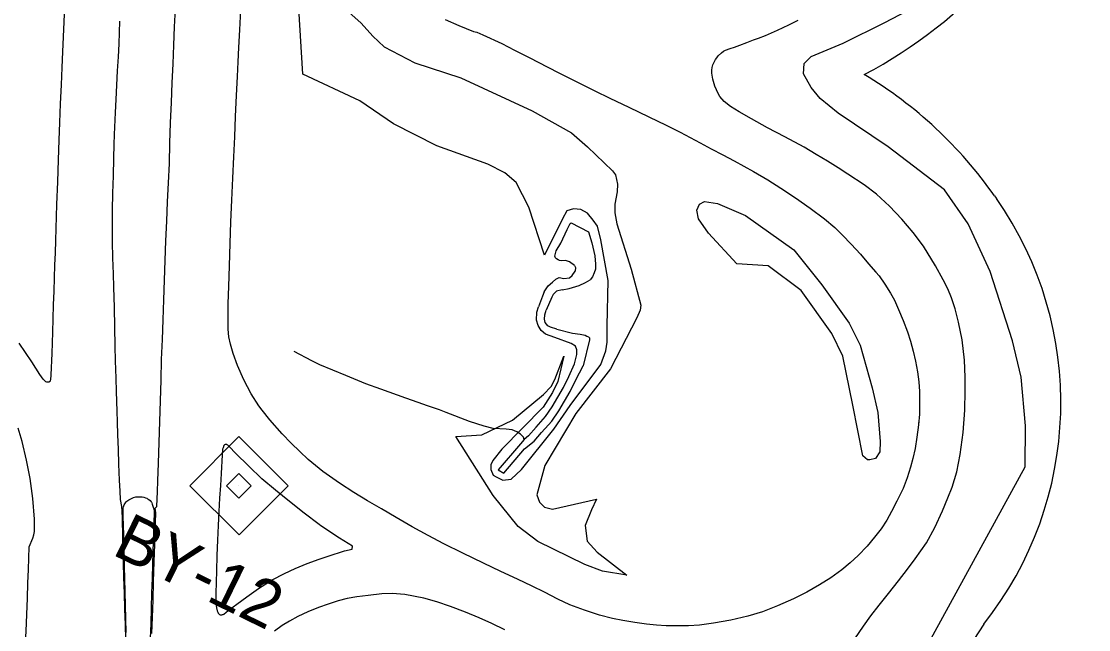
# Model space of a CAD drawing. Extents: x 1517485 to 1521905, y 636528 to 640355.
# Drawn here: x 1520407.4 to 1520862.3, y 637785.1 to 638044.5 of the extents above; entities that cross this region are included whole.
import ezdxf

# ---------------------------------------------------------------- set-up
doc = ezdxf.new("R2010")
doc.units = 0
for name, color, linetype in [('CTL Secondary Horizontal and Vertical CELL', 7, 'Continuous'), ('CTL Secondary Horizontal and Vertical Text', 7, 'Continuous'), ('Default', 7, 'Continuous'), ('Exist Hydro Stream or Body of Water', 7, 'Continuous'), ('Exist Right of Way Line', 7, 'Continuous'), ('Exist Roads Curbs', 7, 'Continuous'), ('Exist Roads EOP', 7, 'Continuous'), ('Exist Vegetation Woods Line', 7, 'Continuous')]:
    doc.layers.add(name, color=color, linetype=linetype)

msp = doc.modelspace()

# ---------------------------------------------------------------- linework, layer by layer
at = {"layer": 'CTL Secondary Horizontal and Vertical CELL'}
msp.add_line((1520500.03, 637846.39), (1520500.03, 637846.39), dxfattribs=at)
msp.add_lwpolyline([(1520479.17, 637846.46), (1520500.14, 637867.42), (1520521.14, 637846.42), (1520500.17, 637825.46)], close=True, dxfattribs=at)
at = {"layer": 'Default'}
msp.add_line((1520500.03, 637846.39), (1520500.03, 637846.39), dxfattribs=at)
msp.add_line((1520500.03, 637846.39), (1520500.03, 637846.39), dxfattribs=at)
msp.add_lwpolyline([(1520494.82, 637846.4), (1520500.06, 637851.65), (1520505.31, 637846.39), (1520500.07, 637841.15)], close=True, dxfattribs=at)
msp.add_lwpolyline([(1520494.82, 637846.4), (1520500.06, 637851.65), (1520505.31, 637846.39), (1520500.07, 637841.15)], close=True, dxfattribs=at)
at = {"layer": 'Exist Hydro Stream or Body of Water'}
for p, q in [((1520641.65, 637907.14), (1520634.82, 637909.65)), ((1520635.6, 637913.25), (1520642.24, 637911.58)), ((1520643.72, 637891.58), (1520646.81, 637897.57)), ((1520623.53, 637867.75), (1520626.75, 637871.47)), ((1520625.94, 637865.54), (1520629.06, 637869.22)), ((1520629.06, 637869.22), (1520632.08, 637872.4))]:
    msp.add_line(p, q, dxfattribs=at)
for points in [[(1520643.09, 637940.4), (1520640.96, 637941.92), (1520639.31, 637942.54), (1520637.48, 637942.35), (1520636.78, 637942.5), (1520636.15, 637942.81), (1520635.41, 637943.18), (1520635.06, 637943.6), (1520634.77, 637944.39), (1520635.38, 637946.69), (1520637.26, 637949.89), (1520640, 637955.7), (1520641.3, 637958.3), (1520641.66, 637958.6), (1520649.15, 637954.74), (1520650.55, 637950.03), (1520651.82, 637944.51), (1520652.08, 637940.93), (1520652.1, 637938.77), (1520651.55, 637937.22), (1520650.87, 637935.54), (1520649.74, 637934.31)], [(1520635.2, 637934.59), (1520636.54, 637935.22), (1520638.55, 637934.83), (1520641.02, 637935.1), (1520642.15, 637936.07), (1520643.35, 637937.94)], [(1520643.09, 637940.4), (1520643.55, 637939.6), (1520643.35, 637937.94)], [(1520630.22, 637929.21), (1520631.98, 637931.68), (1520633.81, 637933.26), (1520635.2, 637934.59)], [(1520637.84, 637930.03), (1520640.87, 637930.54), (1520645.09, 637931.82), (1520647.87, 637933.2), (1520649.74, 637934.31)], [(1520630.22, 637929.21), (1520629.54, 637927.26), (1520627.84, 637922.8)], [(1520637.84, 637930.03), (1520635.45, 637929.38), (1520634, 637928.01), (1520633.42, 637926.83), (1520630.99, 637921.34)], [(1520634.82, 637909.65), (1520630.8, 637911.06), (1520628.9, 637912.69), (1520627.65, 637914.78), (1520626.87, 637917.11), (1520627.08, 637920.45), (1520627.84, 637922.8)], [(1520635.6, 637913.25), (1520632.95, 637914.07), (1520631.72, 637914.71), (1520630.68, 637916.04), (1520630.34, 637917.56), (1520630.46, 637919.39), (1520630.99, 637921.34)], [(1520642.24, 637911.58), (1520645.51, 637911.09), (1520647.73, 637910.66), (1520648.45, 637910.31), (1520649.08, 637909.95), (1520649.47, 637909.58), (1520649.57, 637908.62), (1520646.81, 637897.57)], [(1520643.11, 637898.51), (1520644.16, 637902.41), (1520644.16, 637904.45), (1520643.54, 637905.95), (1520641.65, 637907.14)], [(1520580.5, 637880.56), (1520576.52, 637881.96), (1520571.18, 637883.76), (1520560.54, 637887.71), (1520554.22, 637889.93), (1520545.66, 637893.44), (1520534.65, 637898.05), (1520531.13, 637899.74), (1520523.67, 637903.71)], [(1520626.75, 637871.47), (1520630.82, 637876), (1520633.56, 637880.14), (1520638.38, 637888.3), (1520640.69, 637893.01), (1520643.11, 637898.51)], [(1520632.08, 637872.4), (1520633.47, 637873.95), (1520636.4, 637878.36), (1520641.33, 637886.71), (1520643.72, 637891.58)], [(1520621.71, 637866.12), (1520621.41, 637867.22), (1520620.17, 637868.53), (1520618.61, 637869.42), (1520616.58, 637870.28), (1520613.96, 637870.62), (1520608.43, 637870.93), (1520604.67, 637871.85), (1520598.44, 637873.82), (1520588.37, 637877.66), (1520585.55, 637878.9), (1520580.5, 637880.56)], [(1520620.1, 637864.36), (1520610.6, 637853.21), (1520613.03, 637851.83)], [(1520613.03, 637851.83), (1520621.79, 637862.26), (1520625.94, 637865.54)], [(1520623.53, 637867.75), (1520621.71, 637866.12), (1520620.1, 637864.36)]]:
    msp.add_lwpolyline(points, dxfattribs=at)
at = {"layer": 'Exist Right of Way Line'}
for p, q in [((1520822.17, 637970.08), (1520822.93, 637968.99)), ((1520817.53, 637787.41), (1520776.53, 637724.73))]:
    msp.add_line(p, q, dxfattribs=at)
for centre, radius, start, end in [((1520668.65, 638206.43), 209, 297.9565, 337.8844), ((1520673.07, 637865.71), 182, 34.9928, 59.0667), ((1520698.41, 637881.83), 152, 321.6004, 34.9928)]:
    msp.add_arc(centre, radius, start, end, dxfattribs=at)
at = {"layer": 'Exist Roads Curbs'}
msp.add_lwpolyline([(1520452.09, 637783.92), (1520451.94, 637789.67), (1520451.81, 637795.48), (1520451.67, 637801.22), (1520451.53, 637806.77), (1520451.39, 637812.13), (1520451.13, 637821.98), (1520450.92, 637829.17), (1520450.8, 637833.57), (1520450.8, 637836.2), (1520450.84, 637836.91), (1520450.92, 637837.42), (1520451.04, 637837.9), (1520451.22, 637838.35), (1520451.44, 637838.79), (1520451.71, 637839.19), (1520452.01, 637839.56), (1520452.35, 637839.89), (1520453.14, 637840.44), (1520454.07, 637840.94), (1520455.11, 637841.39), (1520456.14, 637841.67), (1520457.13, 637841.78), (1520458.04, 637841.79), (1520458.86, 637841.7), (1520459.61, 637841.56), (1520460.3, 637841.36), (1520460.92, 637841.1), (1520461.21, 637840.95), (1520461.75, 637840.57), (1520462.28, 637840.11), (1520462.72, 637839.62), (1520462.87, 637839.39), (1520462.98, 637839.19), (1520463.2, 637838.64), (1520463.48, 637837.82), (1520463.74, 637836.96), (1520463.89, 637836.31), (1520463.96, 637835.75), (1520463.96, 637835.15), (1520463.92, 637833.98), (1520463.86, 637831.75), (1520463.72, 637827), (1520463.44, 637818.32), (1520463.27, 637812.82), (1520463.09, 637806.99), (1520462.9, 637800.82), (1520462.71, 637794.32), (1520462.51, 637787.75), (1520462.33, 637781.38)], dxfattribs=at)
at = {"layer": 'Exist Roads EOP'}
msp.add_line((1520789.86, 637872.85), (1520790.06, 637874.32), dxfattribs=at)
for points in [[(1520425.7, 638050.69), (1520425.44, 638044.35), (1520425.19, 638037.92), (1520424.93, 638031.47), (1520424.65, 638024.88), (1520424.34, 638017.47), (1520423.99, 638009.3), (1520423.68, 638001.44), (1520423.39, 637993.88), (1520423.08, 637985.48), (1520422.74, 637976.14), (1520422.41, 637966.35), (1520422.23, 637961.32), (1520422.06, 637956.2), (1520421.89, 637951.03), (1520421.72, 637945.8), (1520421.54, 637940.52), (1520421.36, 637935.09), (1520421.18, 637929.47), (1520420.99, 637923.64), (1520420.79, 637917.61), (1520420.6, 637911.89), (1520420.3, 637902.92), (1520419.96, 637893.73), (1520419.74, 637891.59), (1520419.67, 637891.32), (1520419.59, 637891.12), (1520419.51, 637890.95), (1520419.41, 637890.81), (1520419.3, 637890.71), (1520419.18, 637890.65), (1520419.03, 637890.61), (1520418.85, 637890.59), (1520418.65, 637890.6), (1520418.24, 637890.67), (1520417.88, 637890.8), (1520417.7, 637890.9), (1520417.24, 637891.28), (1520416.65, 637891.91), (1520415.32, 637893.91), (1520411.82, 637899.28), (1520406.45, 637907.26)], [(1520463.03, 637783.49), (1520463.25, 637790.21), (1520463.51, 637797.65), (1520463.77, 637805.65), (1520464.04, 637814.03), (1520464.26, 637821.48), (1520464.54, 637830.76), (1520464.68, 637834.95), (1520464.45, 637836.9), (1520465.13, 637837.58), (1520465.43, 637844.04), (1520465.59, 637848.62), (1520465.83, 637856.06), (1520466.11, 637864.94), (1520466.4, 637873.84), (1520466.68, 637882.72), (1520466.93, 637891.54), (1520467.18, 637900.25), (1520467.47, 637908.81), (1520467.77, 637917.27), (1520468.06, 637925.69), (1520468.36, 637934.09), (1520468.68, 637942.48), (1520469.02, 637950.86), (1520469.37, 637959.23), (1520469.73, 637967.53), (1520470.11, 637975.68), (1520470.45, 637983.94), (1520470.71, 637992.57), (1520470.97, 638001.3), (1520471.33, 638009.88), (1520471.71, 638018.26), (1520472.06, 638026.41), (1520472.39, 638034.38), (1520472.7, 638042.23), (1520473.01, 638049.89)], [(1520588.03, 638045.31), (1520593.88, 638042.77), (1520600.1, 638040.25), (1520600.81, 638040.01), (1520601.54, 638039.85), (1520604.1, 638038.8), (1520612.11, 638035.02), (1520617.62, 638032.27), (1520623.84, 638029.04), (1520631.79, 638024.97), (1520636.47, 638022.6), (1520645.22, 638018.19), (1520651.8, 638014.92), (1520658.19, 638011.81), (1520666.36, 638007.89), (1520674.85, 638003.8), (1520682.22, 638000.21), (1520688.24, 637997.19), (1520696.68, 637992.66), (1520701.36, 637990.18), (1520706.32, 637987.57), (1520711.14, 637985.01), (1520719.41, 637980.53), (1520725.47, 637976.93), (1520731.07, 637973.32), (1520737.32, 637969.25), (1520743.63, 637964.83), (1520749.71, 637960.24), (1520754.15, 637956.53), (1520757.34, 637953.35), (1520761.12, 637949.43), (1520764.97, 637945.16), (1520768.4, 637941.04), (1520771.59, 637937.55), (1520773.03, 637936.01), (1520775.47, 637932.36), (1520777.77, 637928.66), (1520779.54, 637925.65), (1520781.27, 637921.59), (1520783.16, 637916.93), (1520785.08, 637912.16), (1520786.34, 637908.06), (1520787.52, 637903.84), (1520788.46, 637899.55), (1520789.3, 637895.04), (1520789.86, 637890.73), (1520790.12, 637886.62), (1520790.19, 637882.31), (1520790.12, 637876.96), (1520789.77, 637872.51), (1520789.06, 637867.14), (1520788.28, 637862.31), (1520787.39, 637858.09), (1520786.39, 637854.45), (1520784.97, 637849.83), (1520783.15, 637845.22), (1520780.58, 637839.85), (1520778.29, 637835.46), (1520776.2, 637831.78), (1520773.78, 637828.11), (1520771.04, 637824.53), (1520767.84, 637820.7), (1520764.09, 637816.75), (1520760.67, 637813.6), (1520757.03, 637810.64), (1520752.37, 637807.25), (1520747.61, 637804.22), (1520742.21, 637801.02), (1520736.47, 637798.18), (1520729.68, 637795.19), (1520723.24, 637792.74), (1520716.96, 637790.83), (1520709.81, 637789.2), (1520702.33, 637787.84), (1520696.42, 637787.03), (1520691.73, 637786.72), (1520686.93, 637786.66), (1520682.2, 637786.75), (1520678.04, 637787.04), (1520673.82, 637787.47), (1520668.83, 637788.19), (1520663.8, 637788.97), (1520659.3, 637789.87), (1520653.85, 637791.27), (1520647.45, 637793.36), (1520641.09, 637795.71), (1520635.99, 637798.09), (1520630.29, 637801.14), (1520625.08, 637803.7), (1520618.82, 637806.65), (1520611.69, 637809.86), (1520604.36, 637813.45), (1520595.51, 637817.77), (1520587.42, 637821.68), (1520580.76, 637825.25), (1520573.93, 637828.99), (1520567.14, 637832.88), (1520560.85, 637836.56), (1520554.92, 637840.04), (1520549.04, 637843.61), (1520542.92, 637847.59), (1520535.93, 637852.6), (1520529.59, 637857.71), (1520526.01, 637861.09), (1520522.43, 637864.59), (1520518.51, 637868.67), (1520513.33, 637874.53), (1520510.01, 637878.65), (1520508.64, 637880.55), (1520505.35, 637885.63), (1520502.19, 637891.58), (1520499.55, 637897.79), (1520497.68, 637902.92), (1520496.52, 637906.87), (1520495.84, 637909.97), (1520495.48, 637913.26), (1520495.47, 637918.71), (1520495.59, 637924.12), (1520495.79, 637931.37), (1520496.05, 637940.21), (1520496.36, 637949.75), (1520496.73, 637959.07), (1520497.13, 637968.31), (1520497.54, 637977.6), (1520497.93, 637986.68), (1520498.3, 637995.3), (1520498.66, 638003.88), (1520499.07, 638012.86), (1520499.45, 638021.04), (1520499.75, 638027.26), (1520500.05, 638033.29), (1520500.44, 638040.95), (1520500.86, 638049.36)], [(1520449.19, 638044.52), (1520448.87, 638034.99), (1520448.58, 638029.42), (1520448.21, 638023.37), (1520447.89, 638017.24), (1520447.64, 638011.19), (1520447.41, 638005.66), (1520447, 637996.3), (1520446.85, 637992.04), (1520446.67, 637986.17), (1520446.46, 637978.67), (1520446.27, 637971.18), (1520446.1, 637963.98), (1520446.05, 637957.08), (1520446.12, 637950.42), (1520446.29, 637943.64), (1520446.53, 637936.86), (1520446.71, 637931.2), (1520446.93, 637922.46), (1520447.13, 637914.09), (1520447.28, 637906.04), (1520447.32, 637899.71), (1520447.58, 637892.32), (1520447.75, 637886.71), (1520448.07, 637878.21), (1520448.23, 637873.68), (1520448.39, 637868.18), (1520448.59, 637862.04), (1520448.81, 637855.69), (1520449.07, 637848.84), (1520449.32, 637844.18), (1520449.54, 637840.56), (1520450.11, 637837.61), (1520450.24, 637835.77), (1520450.31, 637832.35), (1520450.47, 637824.75), (1520450.61, 637819.51), (1520450.77, 637813.69), (1520450.97, 637807.39), (1520451.18, 637800.7), (1520451.4, 637793.89), (1520451.59, 637787.24), (1520451.76, 637780.84)], [(1520760.81, 637778.53), (1520766.29, 637786.51), (1520769.49, 637790.94), (1520772.99, 637795.51), (1520776.91, 637800.55), (1520781.16, 637805.97), (1520785.03, 637810.93), (1520788.36, 637815.28), (1520793.2, 637822.11), (1520796.67, 637828.59), (1520799.93, 637835.82), (1520802.32, 637841.26), (1520804.08, 637845.85), (1520806.02, 637852.4), (1520807.51, 637859.75), (1520808.77, 637869.15), (1520809.43, 637878.68), (1520809.66, 637886.95), (1520809.69, 637892.73), (1520809.36, 637899.99), (1520808.33, 637908.65), (1520806.83, 637916.28), (1520805.4, 637921.85), (1520803.78, 637926.63), (1520802.23, 637930.37), (1520800.2, 637934.33), (1520797, 637940.3), (1520791.92, 637948.61), (1520787.52, 637954.45), (1520782.68, 637960.11), (1520777.32, 637965.71), (1520771.84, 637970.78), (1520766.65, 637974.74), (1520759.64, 637979.37), (1520755.47, 637982.04), (1520751, 637984.84), (1520746.13, 637987.79), (1520741, 637990.79), (1520732.71, 637995.33), (1520725.43, 637999.16), (1520718.52, 638002.87), (1520713.3, 638005.89), (1520709.59, 638008.25), (1520706.99, 638010.38), (1520705.12, 638012.42), (1520704.33, 638013.7), (1520703.01, 638016.82), (1520702.16, 638019.83), (1520701.73, 638022.43), (1520701.71, 638023.68), (1520701.85, 638024.84), (1520702.15, 638025.91), (1520702.49, 638026.78), (1520703.28, 638028.21), (1520703.74, 638028.99), (1520704.33, 638029.74), (1520705.81, 638031.14), (1520706.61, 638031.74), (1520707.55, 638032.23), (1520709.55, 638032.92), (1520711.26, 638033.49), (1520713.53, 638034.37), (1520716.6, 638035.55), (1520719.45, 638036.56), (1520721.58, 638037.31), (1520724.57, 638038.51), (1520729.6, 638040.74), (1520734.44, 638043.06), (1520738.41, 638045.06)], [(1520407.37, 637757.09), (1520407.5, 637757.78), (1520407.89, 637761.53), (1520408.54, 637771.04), (1520408.96, 637777.5), (1520409.36, 637784.43), (1520409.72, 637791.52), (1520409.99, 637798.46), (1520410.2, 637804.97), (1520410.39, 637810.8), (1520410.76, 637820.38), (1520412.34, 637824.12), (1520412.72, 637825.48), (1520412.93, 637826.93), (1520412.95, 637832.19), (1520412.3, 637840.96), (1520411.15, 637849.53), (1520409.62, 637857.38), (1520407.7, 637865.28), (1520405.99, 637870.96)], [(1520613.49, 637784.95), (1520607.96, 637787.7), (1520602.49, 637790.18), (1520596.67, 637792.55), (1520590.25, 637794.96), (1520584.51, 637796.9), (1520578.87, 637798.45), (1520570.88, 637800.13), (1520565.44, 637800.52), (1520561.08, 637800.34), (1520555.22, 637799.64), (1520550.39, 637799.14), (1520546.3, 637798.42), (1520542.37, 637797.33), (1520538.09, 637796), (1520533.99, 637794.52), (1520529.41, 637792.73), (1520525.24, 637790.65), (1520521.69, 637788.72), (1520518.47, 637786.85), (1520515.23, 637784.47)]]:
    msp.add_lwpolyline(points, dxfattribs=at)
msp.add_lwpolyline([(1520534.38, 637829.92), (1520527.98, 637834.73), (1520521.61, 637839.69), (1520515.66, 637844.51), (1520509.82, 637849.45), (1520504.27, 637854.75), (1520498.59, 637860.41), (1520496.1, 637863.02), (1520495.41, 637863.72), (1520495.12, 637863.92), (1520494.96, 637864), (1520494.78, 637864.04), (1520494.59, 637864.06), (1520494.39, 637864.04), (1520494.2, 637863.99), (1520494.02, 637863.89), (1520493.87, 637863.75), (1520493.74, 637863.56), (1520493.33, 637862.65), (1520493.17, 637862.1), (1520492.94, 637859.71), (1520492.51, 637851.68), (1520492.21, 637846.62), (1520491.9, 637841.18), (1520491.59, 637835.49), (1520491.29, 637829.51), (1520491, 637823.2), (1520490.73, 637816.71), (1520490.5, 637810.15), (1520490.24, 637800.5), (1520490.32, 637796.2), (1520490.57, 637794.34), (1520490.89, 637793.12), (1520491.08, 637792.57), (1520491.3, 637792.13), (1520491.42, 637791.94), (1520491.55, 637791.78), (1520491.71, 637791.64), (1520491.88, 637791.52), (1520492.07, 637791.44), (1520492.29, 637791.39), (1520492.53, 637791.39), (1520492.8, 637791.43), (1520493.08, 637791.5), (1520493.36, 637791.61), (1520493.63, 637791.76), (1520494.68, 637792.52), (1520496.14, 637793.67), (1520499.18, 637795.98), (1520503.51, 637799.07), (1520508.51, 637802.58), (1520514.31, 637806.34), (1520519.47, 637809.1), (1520524.13, 637811.24), (1520529.16, 637813.27), (1520534.35, 637815.11), (1520539.47, 637816.79), (1520543.82, 637818.29), (1520545.15, 637818.73), (1520548.34, 637819.42), (1520548.48, 637820.66), (1520542.95, 637824.11), (1520535.07, 637829.42)], close=True, dxfattribs=at)
at = {"layer": 'Exist Vegetation Woods Line'}
for points in [[(1520665.41, 637808.32), (1520655.08, 637810.1), (1520647.55, 637812.9), (1520627.55, 637822.71), (1520619.13, 637829.15), (1520608.41, 637842.37), (1520592.58, 637867.51), (1520603.7, 637868.17), (1520616.75, 637874.39), (1520629.92, 637885.33), (1520633.25, 637888.78), (1520634.73, 637891.74), (1520638.54, 637901.78), (1520636.06, 637890.96), (1520633.79, 637886.2), (1520629.75, 637879.92), (1520612.1, 637862.13), (1520608.36, 637857.25), (1520607.42, 637855.34), (1520607.51, 637853.35), (1520608.41, 637850.96), (1520609.81, 637850.23), (1520612.56, 637848.88), (1520616.08, 637849.2), (1520620.51, 637853.46), (1520634.37, 637870.6), (1520641.23, 637880.72), (1520654.32, 637898.12), (1520656.46, 637904.02), (1520657, 637907.75), (1520657.08, 637914.69), (1520657.44, 637933.96), (1520654.35, 637951.28), (1520653, 637957.15), (1520651.13, 637959.77), (1520648.7, 637962.68), (1520645.77, 637964.33), (1520642.66, 637964.61), (1520639.82, 637963.75), (1520637.96, 637960.25), (1520630.36, 637944.75), (1520623.6, 637965.3), (1520618.21, 637975.85), (1520613.47, 637979.93), (1520606.25, 637983.66), (1520584.43, 637991.4), (1520565.94, 638000.78), (1520551.64, 638010.66), (1520527.36, 638021.95), (1520524.89, 638061.73)], [(1520835.15, 637854.49), (1520835.3, 637872.01), (1520833.5, 637892.76), (1520829.84, 637908.22), (1520820.24, 637937.86), (1520810.92, 637958.11), (1520800.8, 637972.65), (1520776.89, 637991.05), (1520755.55, 638005.29), (1520747.84, 638011.64), (1520744.03, 638016.3), (1520740.73, 638022.06), (1520741.04, 638026.53), (1520743.98, 638029.47), (1520757.59, 638035.23), (1520775.44, 638043.96), (1520800.09, 638057.16)], [(1520544.24, 638050.88), (1520552.27, 638043.76), (1520557.14, 638038.14), (1520561.96, 638033.65), (1520575.11, 638026.86), (1520594.75, 638020.4), (1520625.15, 638006.39), (1520641.83, 637996.95), (1520648.7, 637991.03), (1520659.32, 637980.78), (1520660.61, 637979.09), (1520661.46, 637975.03), (1520661.34, 637971.8), (1520660.29, 637966.51), (1520660.37, 637962.92), (1520661.24, 637958.17), (1520667.35, 637938.8), (1520671.36, 637923.48), (1520671.17, 637921.36), (1520669.75, 637918.14), (1520658.46, 637896.28), (1520643.72, 637877.33), (1520630.44, 637855.11), (1520627.09, 637842.64), (1520628.19, 637839.45), (1520630.36, 637837.33), (1520633.79, 637836.41), (1520652.54, 637840.67), (1520650.34, 637836.19), (1520647.75, 637829.53), (1520648.48, 637822.84), (1520652.85, 637818.16), (1520665.41, 637808.32)], [(1520765.97, 637859.24), (1520761.77, 637880.83), (1520757.55, 637901.79), (1520752.77, 637911.45), (1520739.72, 637929.7), (1520725.66, 637940.21), (1520712.26, 637941.07), (1520700.22, 637954.14), (1520695.94, 637960.33), (1520695.23, 637964.03), (1520696.48, 637966.6), (1520698.54, 637967.71), (1520704.12, 637966.8), (1520716.04, 637961.66), (1520736.59, 637947.03), (1520748.53, 637932.2), (1520760.23, 637915.78), (1520764.91, 637906.48), (1520770.02, 637888.22), (1520772.41, 637877.67), (1520773.39, 637865.31), (1520773.3, 637860.89), (1520771.36, 637858.03), (1520769.05, 637857.51), (1520768.01, 637857.48), (1520765.97, 637859.24)], [(1520763.42, 637701.14), (1520763.38, 637708.21), (1520763.5, 637714.78), (1520764.37, 637721.48), (1520766.84, 637728.8), (1520769.88, 637734.98), (1520773.01, 637741.3), (1520783.78, 637760.55), (1520835.15, 637854.49)]]:
    msp.add_lwpolyline(points, dxfattribs=at)

# ---------------------------------------------------------------- texts
at = {"layer": 'CTL Secondary Horizontal and Vertical Text'}
msp.add_text('BY-12', height=20, rotation=333.9377, dxfattribs=at).set_placement((1520445.53, 637817.38))

doc.saveas('drawing.dxf')
